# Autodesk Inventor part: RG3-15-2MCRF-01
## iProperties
Created: 2008-09
Part Number: RG3-15-2MCRF-01
Material: 1.0037 St 37-2
Document SubType Name: Modellieren
Designer: TMT
Manufacturer: Standard
Standards Organization: Custom
Density: 7.85 g/cm^3
Mass: 2499.76 g
Surface Area: 403.945 cm^2
Volume: 318.441 cm^3
Author: TMT
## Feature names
1. Extrusion2
2. Bohrung1 [Hole]
3. Extrusion3
4. Extrusion4
5. Extrusion5
6. Extrusion6
7. Rechteckige Anordnung1 [Rectangular Pattern]
8. Extrusion7
9. Extrusion8
10. Rechteckige Anordnung2 [Rectangular Pattern]
11. Bohrung2 [Hole]
12. Bohrung3 [Hole]
13. Spiegeln1 [Mirror]
14. Bohrung4 [Hole]
15. Spiegeln2 [Mirror]
